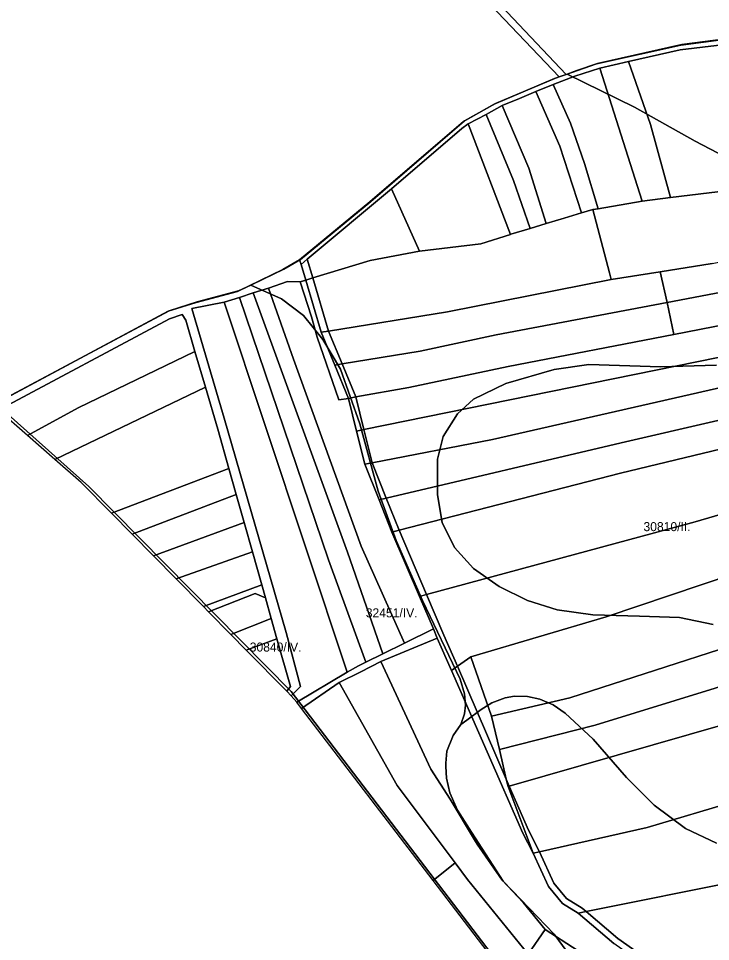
# Model space of a CAD drawing. Extents: x -535894 to -532834, y -1165802 to -1163645.
# Drawn here: x -535420 to -535038, y -1165071 to -1164561 of the extents above; entities that cross this region are included whole.
import ezdxf

# ---------------------------------------------------------------- set-up
doc = ezdxf.new("R2010")
doc.units = 0
for name, color, linetype in [('95560013', 7, 'Continuous'), ('95610013', 7, 'Continuous'), ('95620013', 7, 'Continuous'), ('95640013', 7, 'Continuous'), ('95660013', 7, 'Continuous')]:
    doc.layers.add(name, color=color, linetype=linetype)

msp = doc.modelspace()

# ---------------------------------------------------------------- linework, layer by layer
at = {"layer": '95560013'}
for points in [[(-535022.48, -1164574.53), (-535012.94, -1164654.33), (-535060.19, -1164660.03), (-535071.3, -1164619.75), (-535083.39, -1164584.89), (-535054.91, -1164578.48)], [(-535083.39, -1164584.89), (-535071.3, -1164619.75), (-535060.19, -1164660.03), (-535075.97, -1164661.94), (-535099.23, -1164588.45)], [(-535099.23, -1164588.45), (-535075.97, -1164661.94), (-535100.22, -1164666.18), (-535107.76, -1164641.26), (-535115.56, -1164618.94), (-535125.13, -1164597.55), (-535113.13, -1164592.91)], [(-534710.3, -1164588.31), (-534700.55, -1164604.45), (-534706.29, -1164606.67), (-534778.34, -1164641.2), (-534797.89, -1164649.09), (-534877.44, -1164679.92), (-534892.83, -1164685.88), (-534939.12, -1164694.71), (-535062.16, -1164718.07), (-535065.86, -1164701.05), (-535037.23, -1164696.56), (-534989.77, -1164686.82), (-534905.84, -1164671.7), (-534882.51, -1164664.49), (-534867.62, -1164659.87), (-534813.38, -1164637)], [(-535125.13, -1164597.55), (-535115.56, -1164618.94), (-535107.76, -1164641.26), (-535100.22, -1164666.18), (-535103.22, -1164666.7), (-535109.38, -1164668.56), (-535121.44, -1164631.71), (-535134.56, -1164601.46)], [(-535134.56, -1164601.46), (-535121.44, -1164631.71), (-535109.38, -1164668.56), (-535118.94, -1164671.44), (-535128.9, -1164674.44), (-535138.58, -1164643.8), (-535153.21, -1164609.19), (-535143.69, -1164605.24)], [(-534706.29, -1164606.67), (-534700.55, -1164604.45), (-534690.65, -1164624.3), (-534694.91, -1164625.88), (-534731.01, -1164639.29), (-534823.37, -1164679.09), (-534859.96, -1164692.33), (-534872.36, -1164696.09), (-534891.05, -1164701.75), (-534954.93, -1164716.28), (-534985.67, -1164721.59), (-535058.34, -1164735.63), (-535062.16, -1164718.07), (-534939.12, -1164694.71), (-534892.83, -1164685.88), (-534877.44, -1164679.92), (-534797.89, -1164649.09), (-534778.34, -1164641.2)], [(-535153.21, -1164609.19), (-535138.58, -1164643.8), (-535128.9, -1164674.44), (-535137.84, -1164677.14), (-535147.02, -1164650.67), (-535162.09, -1164614.13)], [(-535162.09, -1164614.13), (-535147.02, -1164650.67), (-535137.84, -1164677.14), (-535148.51, -1164680.35), (-535148.68, -1164680.4), (-535171.93, -1164619.38)], [(-535171.93, -1164619.38), (-535148.68, -1164680.4), (-535165.07, -1164685.54), (-535198.96, -1164689.65), (-535214.35, -1164655.15), (-535175.47, -1164621.86)], [(-534690.65, -1164624.3), (-534680.75, -1164641.94), (-534685.32, -1164643.53), (-534716.28, -1164654.24), (-534820.53, -1164695.61), (-534882.6, -1164715.73), (-534930.6, -1164727.52), (-535229.64, -1164788.31), (-535234.09, -1164770.13), (-535204.83, -1164765.01), (-535150, -1164753.33), (-535058.34, -1164735.63), (-534985.67, -1164721.59), (-534954.93, -1164716.28), (-534891.05, -1164701.75), (-534872.36, -1164696.09), (-534859.96, -1164692.33), (-534823.37, -1164679.09), (-534731.01, -1164639.29), (-534694.91, -1164625.88)], [(-534685.32, -1164643.53), (-534680.75, -1164641.94), (-534669.21, -1164659.89), (-534675.43, -1164661.72), (-534705.37, -1164670.56), (-534787.37, -1164701.01), (-534856.21, -1164724.15), (-534931.28, -1164743.9), (-535012.13, -1164760.48), (-535158.6, -1164793.79), (-535225.1, -1164806.57), (-535229.64, -1164788.31), (-534930.6, -1164727.52), (-534882.6, -1164715.73), (-534820.53, -1164695.61), (-534716.28, -1164654.24)], [(-535198.96, -1164689.65), (-535226.15, -1164694.74), (-535257.9, -1164704.48), (-535260.94, -1164694.17), (-535214.35, -1164655.15)], [(-534669.21, -1164659.89), (-534657.84, -1164675.77), (-534662.44, -1164677.22), (-534691.34, -1164686.36), (-534795.22, -1164722.3), (-534932.16, -1164761.71), (-534978.25, -1164770.31), (-535087.47, -1164795.57), (-535217.32, -1164826.11), (-535225.1, -1164806.57), (-535158.6, -1164793.79), (-535012.13, -1164760.48), (-534931.28, -1164743.9), (-534856.21, -1164724.15), (-534787.37, -1164701.01), (-534705.37, -1164670.56), (-534675.43, -1164661.72)], [(-535109.38, -1164668.56), (-535103.22, -1164666.7), (-535094.01, -1164701.59), (-535093.03, -1164705.31), (-535183.44, -1164723.28), (-535249.16, -1164733.82), (-535257.9, -1164704.48), (-535226.15, -1164694.74), (-535198.96, -1164689.65), (-535165.07, -1164685.54), (-535148.68, -1164680.4), (-535148.51, -1164680.35), (-535137.84, -1164677.14), (-535128.9, -1164674.44), (-535118.94, -1164671.44)], [(-534662.44, -1164677.22), (-534657.84, -1164675.77), (-534648.21, -1164691.35), (-534794.04, -1164738.9), (-534925.58, -1164776.38), (-534981.55, -1164786.79), (-535087.94, -1164812.37), (-535210.21, -1164843.9), (-535217.32, -1164826.11), (-535087.47, -1164795.57), (-534978.25, -1164770.31), (-534932.16, -1164761.71), (-534795.22, -1164722.3), (-534691.34, -1164686.36)], [(-534644.26, -1164706.72), (-534642.29, -1164732.8), (-534729.01, -1164753.95), (-534823.37, -1164779.94), (-534931.7, -1164805.53), (-535046.65, -1164839.34), (-535194.99, -1164879.49), (-535210.21, -1164843.9), (-535087.94, -1164812.37), (-534981.55, -1164786.79), (-534925.58, -1164776.38), (-534794.04, -1164738.9), (-534648.21, -1164691.35)], [(-535065.86, -1164701.05), (-535062.16, -1164718.07), (-535156.56, -1164735.99), (-535198.52, -1164744.91), (-535241.65, -1164751.91), (-535249.16, -1164733.82), (-535183.44, -1164723.28), (-535093.03, -1164705.31)], [(-535062.16, -1164718.07), (-535058.34, -1164735.63), (-535150, -1164753.33), (-535204.83, -1164765.01), (-535234.09, -1164770.13), (-535241.65, -1164751.91), (-535198.52, -1164744.91), (-535156.56, -1164735.99)], [(-534729.01, -1164753.95), (-534642.29, -1164732.8), (-534639.25, -1164772.83), (-534705.71, -1164784.93), (-534805.56, -1164808.33), (-534871.85, -1164826.25), (-534989.4, -1164857.3), (-535007.79, -1164862.16), (-535095.84, -1164891.7), (-535170.48, -1164913.86), (-535177.9, -1164919.08), (-535185.4, -1164901.91), (-535194.99, -1164879.49), (-535046.65, -1164839.34), (-534931.7, -1164805.53), (-534823.37, -1164779.94)], [(-534639.25, -1164772.83), (-534637.67, -1164793.79), (-534635.77, -1164799.17), (-534633.72, -1164804.95), (-534638.54, -1164823.25), (-534671.88, -1164825.83), (-534710.47, -1164830.87), (-534729.94, -1164834.28), (-534841.03, -1164853.81), (-534900.4, -1164867.67), (-534930.69, -1164876.79), (-534980.06, -1164892.73), (-535115.81, -1164936.57), (-535159.15, -1164946.66), (-535170.48, -1164913.86), (-535095.84, -1164891.7), (-535007.79, -1164862.16), (-534989.4, -1164857.3), (-534871.85, -1164826.25), (-534805.56, -1164808.33), (-534705.71, -1164784.93)], [(-534729.94, -1164834.28), (-534710.47, -1164830.87), (-534705.37, -1164856.07), (-534723.79, -1164857.99), (-534825.11, -1164873.81), (-534922.64, -1164896.44), (-535101.94, -1164951.67), (-535154.63, -1164965.06), (-535159.15, -1164946.66), (-535115.81, -1164936.57), (-534980.06, -1164892.73), (-534930.69, -1164876.79), (-534900.4, -1164867.67), (-534841.03, -1164853.81)], [(-534705.37, -1164856.07), (-534641.49, -1164849.43), (-534643.23, -1164857.71), (-534659.18, -1164861.96), (-534703.62, -1164873.54), (-534701.97, -1164880.31), (-534743.37, -1164885.15), (-534834.28, -1164898.95), (-534885.94, -1164910.64), (-534961.47, -1164930.35), (-535010.08, -1164945.35), (-535149.32, -1164985.4), (-535151, -1164981.54), (-535154.63, -1164965.06), (-535101.94, -1164951.67), (-534922.64, -1164896.44), (-534825.11, -1164873.81), (-534723.79, -1164857.99)], [(-535170.48, -1164913.86), (-535159.15, -1164946.66), (-535154.63, -1164965.06), (-535151, -1164981.54), (-535177.9, -1164919.08)], [(-534961.47, -1164930.35), (-534956.54, -1164949.5), (-534955.68, -1164952.84), (-534950.5, -1164972.92), (-534974.01, -1164978.76), (-535073.21, -1165008.15), (-535132.68, -1165021.61), (-535138.71, -1165009.74), (-535149.32, -1164985.4), (-535010.08, -1164945.35)], [(-534691.31, -1164930.67), (-534659.02, -1164930.05), (-534658.67, -1164944.77), (-534658.09, -1164968.25), (-534657.76, -1164976.32), (-534659.02, -1164979.39), (-534688.38, -1164981.11), (-534776.34, -1164986.27), (-534840.9, -1164993.6), (-534911.68, -1165008.4), (-534961.7, -1165023.3), (-535020.48, -1165037.2), (-535106.82, -1165054.65), (-535109.11, -1165052.7), (-535117.6, -1165047.48), (-535124.68, -1165038.88), (-535132.68, -1165021.61), (-535073.21, -1165008.15), (-534974.01, -1164978.76), (-534950.5, -1164972.92), (-534897.39, -1164959.74), (-534814.82, -1164942.8), (-534736.79, -1164933.73)], [(-534688.38, -1164981.11), (-534659.02, -1164979.39), (-534659.81, -1164981.95), (-534655.57, -1165032.56), (-534724.66, -1165029.47), (-534765.23, -1165030.38), (-534811.29, -1165033.87), (-534889.63, -1165046.79), (-534952.44, -1165063.23), (-534984.36, -1165073.72), (-535013.06, -1165078.91), (-535040.34, -1165080.81), (-535067.25, -1165085.28), (-535068.17, -1165084.42), (-535089.33, -1165069.61), (-535106.82, -1165054.65), (-535020.48, -1165037.2), (-534961.7, -1165023.3), (-534911.68, -1165008.4), (-534840.9, -1164993.6), (-534776.34, -1164986.27)]]:
    msp.add_lwpolyline(points, close=True, dxfattribs=at)
msp.add_lwpolyline([(-535037.23, -1164696.56), (-535065.86, -1164701.05), (-535093.03, -1164705.31), (-535094.01, -1164701.59), (-535103.22, -1164666.7), (-535100.22, -1164666.18), (-535075.97, -1164661.94), (-535060.19, -1164660.03), (-535012.94, -1164654.33)], dxfattribs=at)
at = {"layer": '95610013'}
for points in [[(-535434.81, -1164774.69), (-535337.8, -1164722.86), (-535322.24, -1164718.04), (-535299.42, -1164711.94), (-535274.36, -1164699.8), (-535265.14, -1164694.54), (-535264.28, -1164696.97), (-535261.71, -1164705.66), (-535264.79, -1164706.6), (-535271.8, -1164706.52), (-535282.32, -1164710.05), (-535290.79, -1164712.78), (-535298.39, -1164715.22), (-535306.74, -1164717.91), (-535324.72, -1164721.28), (-535306.74, -1164781.96), (-535272.55, -1164900.37), (-535264.58, -1164930.21), (-535269.72, -1164935.43), (-535272.25, -1164932.85), (-535270.21, -1164930.28), (-535277.63, -1164903.97), (-535280.81, -1164892.67), (-535284.01, -1164881.32), (-535286.04, -1164874.13), (-535291.17, -1164855.92), (-535295.73, -1164839.71), (-535300.1, -1164824.22), (-535304.15, -1164809.81), (-535310.26, -1164788.12), (-535317.16, -1164764.78), (-535322.98, -1164745.04), (-535328.05, -1164727.88), (-535330.07, -1164724.66), (-535336.95, -1164727.03), (-535431.57, -1164777.51)], [(-535102.38, -1165082.03), (-535129.39, -1165064.5), (-535141.65, -1165049.71), (-535153.27, -1165037.38), (-535167.09, -1165017.44), (-535168.5, -1165015.08), (-535181.9, -1164992.48), (-535192.57, -1164975.97), (-535220.19, -1164916.49), (-535189.08, -1164903.47), (-535181.28, -1164921.44), (-535141.82, -1165011.33), (-535136.18, -1165022.4), (-535127.67, -1165040.76), (-535119.93, -1165050.16), (-535111.17, -1165055.54), (-535091.48, -1165072.37)]]:
    msp.add_lwpolyline(points, dxfattribs=at)
for points in [[(-535271.8, -1164706.52), (-535264.79, -1164706.6), (-535258.52, -1164725.9), (-535255.52, -1164737.11), (-535243.38, -1164771.85), (-535238.13, -1164771.01), (-535233.62, -1164789.13), (-535229.1, -1164807.35), (-535221.25, -1164827.04), (-535214.13, -1164844.92), (-535198.89, -1164880.55), (-535191.25, -1164898.41), (-535207.22, -1164906.27), (-535231.08, -1164852.62), (-535268.57, -1164749.4), (-535282.32, -1164710.05)], [(-535264.79, -1164706.6), (-535261.71, -1164705.66), (-535253.23, -1164734.48), (-535245.75, -1164752.59), (-535238.13, -1164771.01), (-535243.38, -1164771.85), (-535255.52, -1164737.11), (-535258.52, -1164725.9)], [(-535298.39, -1164715.22), (-535290.79, -1164712.78), (-535238.67, -1164856.05), (-535219.2, -1164912.17), (-535228.61, -1164916.81), (-535249.1, -1164860.22)], [(-535290.79, -1164712.78), (-535282.32, -1164710.05), (-535268.57, -1164749.4), (-535231.08, -1164852.62), (-535207.22, -1164906.27), (-535219.2, -1164912.17), (-535238.67, -1164856.05)], [(-535324.72, -1164721.28), (-535306.74, -1164717.91), (-535238.77, -1164922.41), (-535266.73, -1164938.9), (-535269.72, -1164935.43), (-535264.58, -1164930.21), (-535272.55, -1164900.37), (-535306.74, -1164781.96)], [(-535306.74, -1164717.91), (-535298.39, -1164715.22), (-535249.1, -1164860.22), (-535228.61, -1164916.81), (-535232.65, -1164918.79), (-535238.77, -1164922.41)], [(-535336.95, -1164727.03), (-535330.07, -1164724.66), (-535328.05, -1164727.88), (-535322.98, -1164745.04), (-535387.55, -1164776.28), (-535415.52, -1164791.51), (-535431.57, -1164777.51)], [(-535322.98, -1164745.04), (-535317.16, -1164764.78), (-535400.34, -1164804.75), (-535415.52, -1164791.51), (-535387.55, -1164776.28)], [(-535317.16, -1164764.78), (-535310.26, -1164788.12), (-535304.15, -1164809.81), (-535369, -1164834.5), (-535385.74, -1164817.49), (-535400.34, -1164804.75)], [(-535304.15, -1164809.81), (-535300.1, -1164824.22), (-535357.66, -1164846.04), (-535369, -1164834.5)], [(-535300.1, -1164824.22), (-535295.73, -1164839.71), (-535345.77, -1164858.11), (-535357.66, -1164846.04)], [(-535295.73, -1164839.71), (-535291.17, -1164855.92), (-535333.29, -1164870.81), (-535345.77, -1164858.11)], [(-535333.29, -1164870.81), (-535291.17, -1164855.92), (-535286.04, -1164874.13), (-535318.27, -1164886.08)], [(-535286.04, -1164874.13), (-535284.01, -1164881.32), (-535289.62, -1164878.78), (-535315.47, -1164888.93), (-535318.27, -1164886.08)], [(-535289.62, -1164878.78), (-535284.01, -1164881.32), (-535280.81, -1164892.67), (-535303.11, -1164901.49), (-535315.47, -1164888.93)], [(-535303.11, -1164901.49), (-535280.81, -1164892.67), (-535277.63, -1164903.97), (-535294.62, -1164910.11)], [(-535191.25, -1164898.41), (-535189.08, -1164903.47), (-535220.19, -1164916.49), (-535231.36, -1164922.07), (-535243.3, -1164928.03), (-535264.1, -1164942.33), (-535266.73, -1164938.9), (-535238.77, -1164922.41), (-535232.65, -1164918.79), (-535228.61, -1164916.81), (-535219.2, -1164912.17), (-535207.22, -1164906.27)], [(-535294.62, -1164910.11), (-535277.63, -1164903.97), (-535270.21, -1164930.28), (-535272.25, -1164932.85)], [(-535220.19, -1164916.49), (-535192.57, -1164975.97), (-535181.9, -1164992.48), (-535168.5, -1165015.08), (-535167.09, -1165017.44), (-535153.27, -1165037.38), (-535141.65, -1165049.71), (-535129.39, -1165064.5), (-535138.85, -1165078.22), (-535172.47, -1165036.89), (-535179.28, -1165027.8), (-535211.27, -1164985.05), (-535243.3, -1164928.03), (-535231.36, -1164922.07)], [(-535243.3, -1164928.03), (-535211.27, -1164985.05), (-535179.28, -1165027.8), (-535191.37, -1165037.5), (-535264.1, -1164942.33)], [(-535179.28, -1165027.8), (-535172.47, -1165036.89), (-535138.85, -1165078.22), (-535141.75, -1165082.45), (-535149, -1165092.96), (-535191.37, -1165037.5)], [(-535138.85, -1165078.22), (-535129.39, -1165064.5), (-535102.38, -1165082.03), (-535080.8, -1165098.36), (-535076.07, -1165102.38), (-535091.8, -1165120.03), (-535141.75, -1165082.45)]]:
    msp.add_lwpolyline(points, close=True, dxfattribs=at)
at = {"layer": '95620013'}
for points in [[(-535644.3, -1164037.06), (-535329.29, -1164368.36), (-535086.95, -1164143.16), (-535085.71, -1164144.07), (-535085.14, -1164146.96), (-535326.28, -1164371.53), (-535117.95, -1164592.03), (-535121.76, -1164593.37), (-535329.84, -1164374.82), (-535605.04, -1164629.61), (-535608.87, -1164626.28), (-535332.86, -1164371.64), (-535474.5, -1164222.2), (-535476.52, -1164220.08), (-535649.36, -1164037.73)], [(-535121.76, -1164593.37), (-535124.4, -1164594.3), (-535157.57, -1164608.35), (-535174.63, -1164617.97), (-535226.37, -1164662.4), (-535265.14, -1164694.54), (-535274.36, -1164699.8), (-535299.42, -1164711.94), (-535322.24, -1164718.04), (-535337.8, -1164722.86), (-535434.81, -1164774.69), (-535538.55, -1164687.07), (-535605.04, -1164629.61), (-535329.84, -1164374.82)]]:
    msp.add_lwpolyline(points, close=True, dxfattribs=at)
msp.add_lwpolyline([(-534926.03, -1164558.08), (-534936.2, -1164561.96), (-534946.31, -1164563.69), (-534957.79, -1164565.07), (-535001.64, -1164568.89), (-535054.61, -1164575.73), (-535101.2, -1164586.14), (-535117.95, -1164592.03), (-535326.28, -1164371.53)], dxfattribs=at)
at = {"layer": '95640013'}
msp.add_lwpolyline([(-535022.48, -1164574.53), (-535054.91, -1164578.48), (-535083.39, -1164584.89), (-535099.23, -1164588.45), (-535113.13, -1164592.91), (-535125.13, -1164597.55), (-535134.56, -1164601.46), (-535143.69, -1164605.24), (-535153.21, -1164609.19), (-535162.09, -1164614.13), (-535171.93, -1164619.38), (-535175.47, -1164621.86), (-535214.35, -1164655.15), (-535260.94, -1164694.17), (-535264.28, -1164696.97), (-535265.14, -1164694.54), (-535226.37, -1164662.4), (-535174.63, -1164617.97), (-535157.57, -1164608.35), (-535124.4, -1164594.3), (-535121.76, -1164593.37), (-535117.95, -1164592.03), (-535101.2, -1164586.14), (-535054.61, -1164575.73), (-535001.64, -1164568.89)], dxfattribs=at)
for points in [[(-535260.94, -1164694.17), (-535257.9, -1164704.48), (-535261.71, -1164705.66), (-535264.28, -1164696.97)], [(-535261.71, -1164705.66), (-535257.9, -1164704.48), (-535249.16, -1164733.82), (-535253.23, -1164734.48)], [(-535249.16, -1164733.82), (-535241.65, -1164751.91), (-535245.75, -1164752.59), (-535253.23, -1164734.48)], [(-535245.75, -1164752.59), (-535241.65, -1164751.91), (-535234.09, -1164770.13), (-535238.13, -1164771.01)], [(-535238.13, -1164771.01), (-535234.09, -1164770.13), (-535229.64, -1164788.31), (-535233.62, -1164789.13)], [(-535233.62, -1164789.13), (-535229.64, -1164788.31), (-535225.1, -1164806.57), (-535229.1, -1164807.35)], [(-535225.1, -1164806.57), (-535217.32, -1164826.11), (-535221.25, -1164827.04), (-535229.1, -1164807.35)], [(-535221.25, -1164827.04), (-535217.32, -1164826.11), (-535210.21, -1164843.9), (-535214.13, -1164844.92)], [(-535210.21, -1164843.9), (-535194.99, -1164879.49), (-535198.89, -1164880.55), (-535214.13, -1164844.92)], [(-535198.89, -1164880.55), (-535194.99, -1164879.49), (-535185.4, -1164901.91), (-535177.9, -1164919.08), (-535181.28, -1164921.44), (-535189.08, -1164903.47), (-535191.25, -1164898.41)], [(-535177.9, -1164919.08), (-535151, -1164981.54), (-535150.55, -1164983.6), (-535149.83, -1164985.54), (-535136.18, -1165022.4), (-535141.82, -1165011.33), (-535181.28, -1164921.44)], [(-535150.55, -1164983.6), (-535151, -1164981.54), (-535149.32, -1164985.4), (-535149.83, -1164985.54)], [(-535149.32, -1164985.4), (-535138.71, -1165009.74), (-535132.68, -1165021.61), (-535136.18, -1165022.4), (-535149.83, -1164985.54)], [(-535136.18, -1165022.4), (-535132.68, -1165021.61), (-535124.68, -1165038.88), (-535117.6, -1165047.48), (-535109.11, -1165052.7), (-535106.82, -1165054.65), (-535111.17, -1165055.54), (-535119.93, -1165050.16), (-535127.67, -1165040.76)], [(-535111.17, -1165055.54), (-535106.82, -1165054.65), (-535089.33, -1165069.61), (-535068.17, -1165084.42), (-535067.25, -1165085.28), (-535071.93, -1165086.06), (-535091.48, -1165072.37)]]:
    msp.add_lwpolyline(points, close=True, dxfattribs=at)
at = {"layer": '95660013'}
for points in [[(-534930.369, -1164559.695), (-534935.616, -1164561.701), (-534945.728, -1164563.423), (-534957.21, -1164564.802), (-535000, -1164568.532), (-535001.057, -1164568.625), (-535054.023, -1164575.458), (-535100.616, -1164585.868), (-535112.034, -1164589.882), (-535117.371, -1164591.759), (-535121.179, -1164593.097), (-535123.817, -1164594.021), (-535156.991, -1164608.077), (-535174.047, -1164617.688), (-535225.782, -1164662.124), (-535264.558, -1164694.259), (-535273.775, -1164699.521), (-535285.222, -1164705.064), (-535292.152, -1164708.42), (-535298.828, -1164711.653), (-535321.651, -1164717.756), (-535337.207, -1164722.574), (-535394.549, -1164753.205), (-535432.662, -1164773.563)], [(-535008.91, -1164648.51), (-535046.58, -1164628.92), (-535080.19, -1164610.13), (-535117.371, -1164591.759), (-535112.034, -1164589.882), (-535100.616, -1164585.868), (-535054.023, -1164575.458), (-535001.057, -1164568.625)], [(-535034.832, -1165016.773), (-535051.92, -1165008.759), (-535069.28, -1164995.86), (-535084.573, -1164980.567), (-535102.89, -1164959.39), (-535118.5, -1164945.05), (-535125.03, -1164940.43), (-535132.363, -1164937.234), (-535139.28, -1164935.73), (-535146.358, -1164935.645), (-535151.63, -1164936.61), (-535158.869, -1164939.32), (-535164.77, -1164942.9), (-535172.81, -1164948.87), (-535176.08, -1164951.26), (-535174.08, -1164945.29), (-535173.45, -1164940.59), (-535174, -1164934.22), (-535176.39, -1164926.18), (-535197.26, -1164882.69), (-535211.75, -1164849.56), (-535221.79, -1164822.33), (-535231.819, -1164785.06), (-535242.49, -1164754.951), (-535252.21, -1164738.55), (-535263.04, -1164725.17), (-535275.15, -1164716.09), (-535292.152, -1164708.42), (-535285.222, -1164705.064), (-535273.775, -1164699.521), (-535264.558, -1164694.259), (-535225.782, -1164662.124), (-535174.047, -1164617.688), (-535156.991, -1164608.077), (-535123.817, -1164594.021), (-535121.179, -1164593.097), (-535117.371, -1164591.759), (-535080.19, -1164610.13), (-535046.58, -1164628.92), (-535008.91, -1164648.51)], [(-535432.662, -1164773.563), (-535394.549, -1164753.205), (-535337.207, -1164722.574), (-535321.651, -1164717.756), (-535298.828, -1164711.653), (-535292.152, -1164708.42), (-535275.15, -1164716.09), (-535263.04, -1164725.17), (-535252.21, -1164738.55), (-535242.49, -1164754.951), (-535231.819, -1164785.06), (-535221.79, -1164822.33), (-535211.75, -1164849.56), (-535197.26, -1164882.69), (-535176.39, -1164926.18), (-535174, -1164934.22), (-535173.45, -1164940.59), (-535174.08, -1164945.29), (-535176.08, -1164951.26), (-535180.3, -1164957.4), (-535183.72, -1164965.92), (-535184.44, -1164972.69), (-535184.339, -1164974.424), (-535183.96, -1164980.97), (-535182.066, -1164989.044), (-535177.91, -1164998.65), (-535170.1, -1165010.75), (-535152.608, -1165037.849), (-535142.87, -1165048.02), (-535124.571, -1165067.131), (-535110.05, -1165086.73)], [(-535036.71, -1164896.031), (-535055.17, -1164892.088), (-535077.32, -1164891.41), (-535103.13, -1164890.62), (-535122.767, -1164887.929), (-535139.305, -1164882.655), (-535154.89, -1164875.01), (-535169.047, -1164864.965), (-535179.494, -1164853.513), (-535186.43, -1164839.65), (-535188.98, -1164824.36), (-535188.98, -1164804.61), (-535185.79, -1164792.02), (-535177.99, -1164779.6), (-535169.07, -1164771.48), (-535151.23, -1164762.72), (-535124.47, -1164755.07), (-535105.36, -1164752.36), (-535065.7, -1164753.639), (-535034.79, -1164752.68)], [(-535034.79, -1164752.68), (-535065.7, -1164753.639), (-535105.36, -1164752.36), (-535124.47, -1164755.07), (-535151.23, -1164762.72), (-535169.07, -1164771.48), (-535177.99, -1164779.6), (-535185.79, -1164792.02), (-535188.98, -1164804.61), (-535188.98, -1164824.36), (-535186.43, -1164839.65), (-535179.494, -1164853.513), (-535169.047, -1164864.965), (-535154.89, -1164875.01), (-535139.305, -1164882.655), (-535122.767, -1164887.929), (-535103.13, -1164890.62), (-535077.32, -1164891.41), (-535055.17, -1164892.088), (-535036.71, -1164896.031)], [(-535433.191, -1164773.846), (-535381.625, -1164819.757), (-535269.853, -1164932.956), (-535148.539, -1165091.751)], [(-535148.539, -1165091.751), (-535269.853, -1164932.956), (-535381.625, -1164819.757), (-535433.191, -1164773.846)], [(-535149, -1165092.96), (-535191.37, -1165037.5), (-535264.1, -1164942.33), (-535266.73, -1164938.9), (-535269.72, -1164935.43), (-535272.25, -1164932.85), (-535294.62, -1164910.11), (-535303.11, -1164901.49), (-535315.47, -1164888.93), (-535318.27, -1164886.08), (-535333.29, -1164870.81), (-535345.77, -1164858.11), (-535357.66, -1164846.04), (-535369, -1164834.5), (-535385.74, -1164817.49), (-535400.34, -1164804.75), (-535415.52, -1164791.51), (-535431.57, -1164777.51)], [(-535110.05, -1165086.73), (-535124.571, -1165067.131), (-535142.87, -1165048.02), (-535152.608, -1165037.849), (-535170.1, -1165010.75), (-535177.91, -1164998.65), (-535182.066, -1164989.044), (-535183.96, -1164980.97), (-535184.339, -1164974.424), (-535184.44, -1164972.69), (-535183.72, -1164965.92), (-535180.3, -1164957.4), (-535176.08, -1164951.26), (-535172.81, -1164948.87), (-535164.77, -1164942.9), (-535158.869, -1164939.32), (-535151.63, -1164936.61), (-535146.358, -1164935.645), (-535139.28, -1164935.73), (-535132.363, -1164937.234), (-535125.03, -1164940.43), (-535118.5, -1164945.05), (-535102.89, -1164959.39), (-535084.573, -1164980.567), (-535069.28, -1164995.86), (-535051.92, -1165008.759), (-535034.832, -1165016.773)]]:
    msp.add_lwpolyline(points, dxfattribs=at)

# ---------------------------------------------------------------- texts
for s, p in [('30810/II.', (-535075.156, -1164844.398)), ('32451/IV.', (-535228.575, -1164892.05)), ('30840/IV.', (-535292.681, -1164910.959))]:
    msp.add_text(s, height=5, rotation=360, dxfattribs=at).set_placement(p)

doc.saveas('drawing.dxf')
